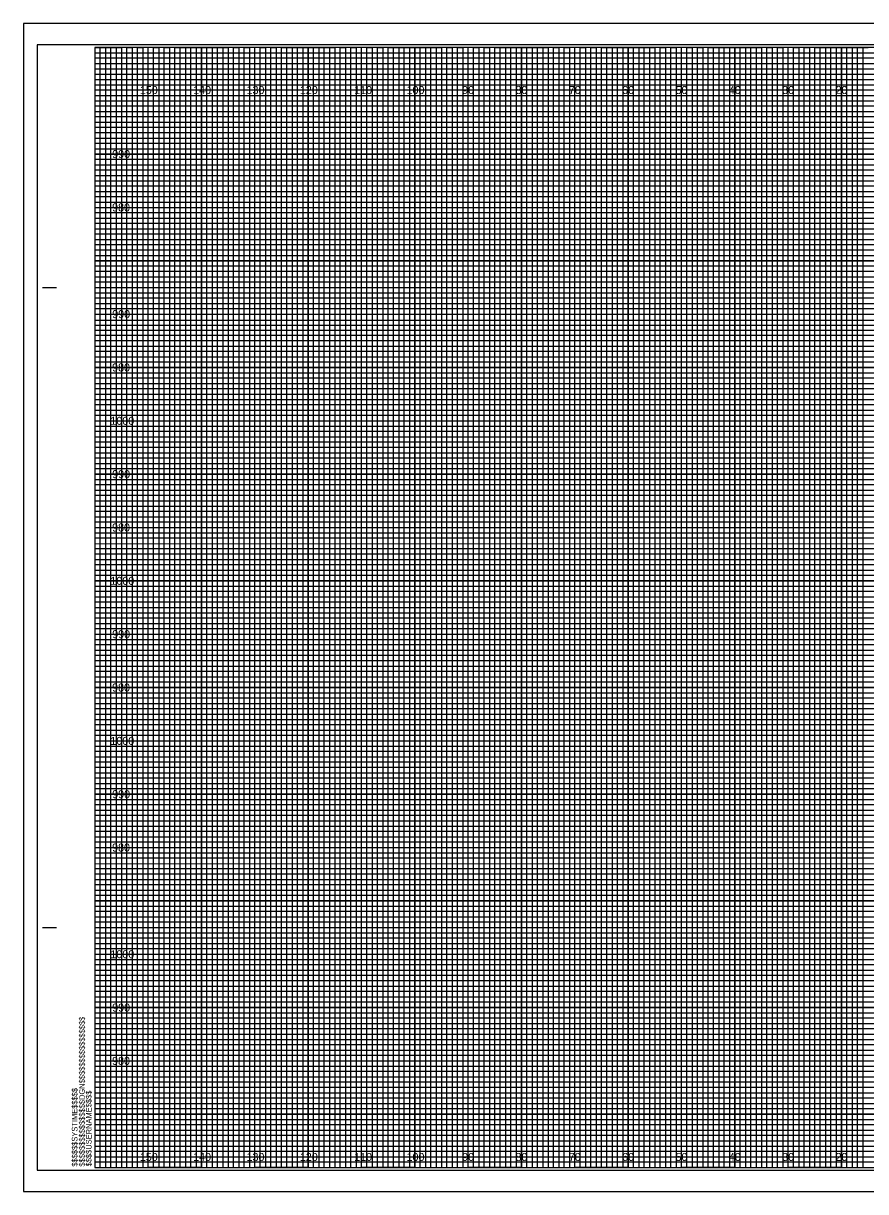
# Model space of a CAD drawing. Extents: x -13 to 323, y -5 to 215.
# Drawn here: x -13.4 to 144.5, y -4.5 to 214.5 of the extents above; entities that cross this region are included whole.
import ezdxf

# ---------------------------------------------------------------- set-up
doc = ezdxf.new("R2010")
doc.units = 0
for name, color, linetype in [('Prop XS Elevation Labels', 7, 'Continuous'), ('Prop XS Offset Labels', 7, 'Continuous'), ('Sheet Cross Section CELL', 7, 'Continuous'), ('Sheet Cross Section Grid Major CELL', 7, 'Continuous'), ('Sheet Cross Section Grid Middle CELL', 7, 'Continuous'), ('Sheet Cross Section Grid Minor 1 CELL', 7, 'Continuous'), ('Sheet Cross Section Grid Minor 2 CELL', 7, 'Continuous'), ('Sheet Cutting Line CELL', 7, 'Continuous'), ('Sheet DOT Grid CELL', 7, 'Continuous'), ('Sheet Plot Border Inside CELL', 7, 'Continuous'), ('Sheet Plot Border Outside CELL', 7, 'Continuous')]:
    doc.layers.add(name, color=color, linetype=linetype)

msp = doc.modelspace()

# ---------------------------------------------------------------- linework, layer by layer
at = {"layer": 'Sheet Cross Section CELL'}
for p, q in [((-9.8, 165), (-7.3, 165)), ((-9.7, 165), (-7.2, 165)), ((-9.8, 45), (-7.3, 45)), ((-9.7, 45), (-7.2, 45))]:
    msp.add_line(p, q, dxfattribs=at)
msp.add_lwpolyline([(320, 210), (0, 210), (0, 0), (320, 0)], close=True, dxfattribs=at)
at = {"layer": 'Sheet Cross Section Grid Major CELL'}
for p, q in [((10, 210), (0, 210)), ((10, 0), (10, 210)), ((30, 210), (20, 210)), ((20, 210), (20, 0)), ((30, 0), (30, 210)), ((50, 210), (40, 210)), ((40, 210), (40, 0)), ((50, 0), (50, 210)), ((70, 210), (60, 210)), ((60, 210), (60, 0)), ((70, 0), (70, 210)), ((90, 210), (80, 210)), ((80, 210), (80, 0)), ((90, 0), (90, 210)), ((110, 210), (100, 210)), ((100, 210), (100, 0)), ((110, 0), (110, 210)), ((130, 210), (120, 210)), ((120, 210), (120, 0)), ((130, 0), (130, 210)), ((150, 210), (140, 210)), ((140, 210), (140, 0)), ((20, 0), (10, 0)), ((40, 0), (30, 0)), ((60, 0), (50, 0)), ((80, 0), (70, 0)), ((100, 0), (90, 0)), ((120, 0), (110, 0)), ((140, 0), (130, 0))]:
    msp.add_line(p, q, dxfattribs=at)
for points in [[(0, 200), (320, 200), (320, 190), (0, 190)], [(0, 180), (320, 180), (320, 170), (0, 170)], [(0, 160), (320, 160), (320, 150), (0, 150)], [(0, 140), (320, 140), (320, 130), (0, 130)], [(0, 120), (320, 120), (320, 110), (0, 110)], [(0, 100), (320, 100), (320, 90), (0, 90)], [(0, 80), (320, 80), (320, 70), (0, 70)], [(0, 60), (320, 60), (320, 50), (0, 50)], [(0, 40), (320, 40), (320, 30), (0, 30)], [(0, 20), (320, 20), (320, 10), (0, 10)]]:
    msp.add_lwpolyline(points, dxfattribs=at)
at = {"layer": 'Sheet Cross Section Grid Middle CELL'}
for points in [[(0, 210), (5, 210), (5, 0), (15, 0), (15, 210), (25, 210), (25, 0), (35, 0), (35, 210), (45, 210), (45, 0), (55, 0), (55, 210), (65, 210), (65, 0), (75, 0), (75, 210), (85, 210), (85, 0), (95, 0), (95, 210), (105, 210), (105, 0), (115, 0), (115, 210), (125, 210), (125, 0), (135, 0), (135, 210), (145, 210)], [(0, 205), (275, 205)], [(0, 185), (320, 185), (320, 195), (0, 195)], [(0, 165), (320, 165), (320, 175), (0, 175)], [(0, 145), (320, 145), (320, 155), (0, 155)], [(0, 125), (320, 125), (320, 135), (0, 135)], [(0, 105), (320, 105), (320, 115), (0, 115)], [(0, 85), (320, 85), (320, 95), (0, 95)], [(0, 65), (320, 65), (320, 75), (0, 75)], [(0, 45), (320, 45), (320, 55), (0, 55)], [(0, 25), (320, 25), (320, 35), (0, 35)], [(0, 5), (320, 5), (320, 15), (0, 15)]]:
    msp.add_lwpolyline(points, dxfattribs=at)
at = {"layer": 'Sheet Cross Section Grid Minor 1 CELL'}
for p, q in [((0, 209), (260, 209)), ((260, 207.98), (0, 207.98)), ((0, 207.98), (0, 207)), ((0, 207), (260, 207)), ((260, 205.89), (0, 205.89)), ((0, 205.89), (0, 204)), ((0, 204), (320, 204))]:
    msp.add_line(p, q, dxfattribs=at)
for points in [[(0, 203), (270, 203), (320, 203), (320, 202), (0, 202)], [(0, 201), (320, 201), (320, 199), (0, 199)], [(0, 198), (320, 198), (320, 197), (0, 196.98)], [(0, 196), (320, 196), (320, 194), (0, 194)], [(0, 193), (320, 193), (320, 192), (0, 192)], [(0, 191), (320, 191), (320, 189), (0, 189)], [(0, 188), (320, 188), (320, 187), (0, 187)], [(0, 186), (320, 186), (320, 184), (0, 184)], [(0, 183), (320, 183), (320, 182), (0, 182)], [(0, 181), (320, 181), (320, 179), (0, 179)], [(0, 178), (320, 178), (320, 177), (0, 177)], [(0, 176), (320, 176), (320, 173.95), (320, 173), (320, 172), (0, 172)], [(0, 174), (320, 174), (320, 173), (0, 173)], [(0, 171), (320, 171), (320, 169), (0, 169.03)], [(0, 169.03), (320, 169), (320, 168), (0, 168)], [(0, 167), (320, 167), (320, 166), (0, 166)], [(0, 164), (320, 164), (320, 163), (0, 163)], [(0, 162), (320, 162), (320, 161), (0, 161)], [(-0.07, 158.89), (320, 158.89), (320, 157.88), (-0.07, 157.88)], [(0, 157), (320, 157), (320, 156), (0, 156)], [(0, 154), (320, 154), (320, 153), (0, 153)], [(0, 152), (320, 152), (320, 151), (0, 151)], [(0, 149), (320, 149), (320, 148), (0, 148)], [(0, 147), (320, 147), (320, 146), (0, 146)], [(0, 144), (320, 144), (320, 143), (0, 143)], [(0, 142), (320, 142), (320, 141), (0, 141)], [(0, 139), (320, 139), (319.99, 137.98), (0, 138)], [(0, 137), (320, 137), (320, 136), (0, 136)], [(0, 134), (320, 134), (320, 133), (0, 133)], [(0, 132), (320, 132), (320, 131), (0, 131)], [(0, 129), (320, 129), (320, 128), (0, 128)], [(0, 127), (320, 127), (320, 126), (0, 126)], [(0, 124), (320, 124), (320, 123), (0, 123)], [(0, 122), (320, 122), (320, 121), (0, 121)], [(0, 119), (320, 119), (320, 118), (0, 118)], [(0, 116.99), (320.07, 116.91), (320, 116), (0, 116)], [(0, 114), (320, 114), (320, 113), (0, 113)], [(0, 112), (320, 112), (320, 111), (0, 111)], [(0, 109), (320, 109), (320, 108), (0, 108)], [(0, 107), (320, 107), (320, 106), (0, 106)], [(0, 104), (320, 104), (320, 103), (0, 103)], [(0, 102), (320, 102), (320, 101), (0, 101)], [(0, 99), (320, 99), (320, 98), (0, 98)], [(0, 97), (320, 97), (320, 96), (0, 96)], [(0, 94), (320, 94), (320, 93), (0, 93)], [(0, 92), (320, 92), (320, 91), (0, 91)], [(0, 89), (320, 89), (320, 88), (0, 88)], [(0, 87), (320, 87), (320, 86), (0, 86)], [(0, 84), (320, 84), (320, 83), (0, 83)], [(0, 82), (320, 82), (320, 81), (0, 81)], [(0, 79), (320, 79), (319.99, 77.98), (0, 78)], [(0, 77), (320, 77), (320, 76), (0, 76)], [(0, 74), (320, 74), (320, 73), (0, 73)], [(0, 72), (320, 72), (320, 71), (0, 71)], [(0, 69), (320, 69), (320, 68), (0, 68)], [(0, 67), (320, 67), (320, 66), (0, 66)], [(0, 64), (320, 64), (320, 63), (0, 63)], [(0, 62), (320, 62), (320, 61), (0, 61)], [(0, 59), (320, 59), (320, 58), (0, 58)], [(0, 56.99), (320.07, 56.91), (320, 56), (0, 56)], [(0, 54), (320, 54), (320, 53), (0, 53)], [(0, 52), (320, 52), (320, 51), (0, 51)], [(0, 49), (320, 49), (320, 48), (0, 48)], [(0, 47), (320, 47), (320, 46), (0, 46)], [(0, 44), (320, 44), (320, 43), (0, 43)], [(0, 42), (320, 42), (320, 41), (0, 41)], [(0, 39), (320, 39), (320, 38), (0, 38)], [(0, 37), (320, 37), (320, 36), (0, 36)], [(0, 34), (320, 34), (320, 33), (0, 33)], [(0, 32), (320, 32), (320, 31), (0, 31)], [(0, 29), (320, 29), (320, 28), (0, 28)], [(0, 27), (320, 27), (320, 26), (0, 26)], [(0, 24), (320, 24), (320, 23), (0, 23)], [(0, 22), (320, 22), (320, 21), (0, 21)], [(0, 19), (320, 19), (320, 18), (0, 18)], [(0, 17), (320, 17), (320, 16), (0, 16)], [(0, 14), (320, 14), (320, 13), (0, 13)], [(0, 12), (320, 12), (320, 11), (0, 11)], [(0, 9), (320, 9), (320, 8), (0, 8)], [(0, 7), (320, 7), (320, 6), (0, 6)], [(0, 4), (320, 4), (320, 3), (0, 3)], [(0, 2), (320, 2), (320, 1), (0, 1)]]:
    msp.add_lwpolyline(points, dxfattribs=at)
at = {"layer": 'Sheet Cross Section Grid Minor 2 CELL'}
for points in [[(0, 0), (1, 0), (1, 210), (2, 210), (2, 0)], [(2, 0), (3, 0), (3, 210), (4, 210), (4, 0)], [(5, 0), (6, 0), (6, 210), (7, 210), (7, 0)], [(7, 0), (8, 0), (8, 210), (9, 210), (9, 0)], [(10, 0), (11, 0), (11, 210), (12, 210), (12, 0)], [(12, 0), (13, 0), (13, 210), (14, 210), (14, 0)], [(15, 0), (16, 0), (16, 210), (17, 210), (17, 0)], [(17, 0), (18, 0), (18, 210), (19, 210), (19, 0)], [(20, 0), (21, 0), (21, 210), (22, 210), (22, 0)], [(22, 0), (23, 0), (23, 210), (24, 210), (24, 0)], [(25, 0), (26, 0), (26, 210), (27, 210), (27, 0)], [(27, 0), (28, 0), (28, 210), (29, 210), (29, 0)], [(30, 0), (31, 0), (31, 210), (32, 210), (32, 0)], [(32, 0), (33, 0), (33, 210), (34, 210), (34, 0)], [(35, 0), (36, 0), (36, 210), (37, 210), (37, 0)], [(37, 0), (38, 0), (38, 210), (39, 210), (39, 0)], [(40, 0), (41, 0), (41, 210), (42, 210), (42, 0)], [(42, 0), (43, 0), (43, 210), (44, 210), (44, 0)], [(45, 0), (46, 0), (46, 210), (47, 210), (47, 0)], [(47, 0), (48, 0), (48, 210), (49, 210), (49, 0)], [(50, 0), (51, 0), (51, 210), (52, 210), (52, 0)], [(52, 0), (53, 0), (53, 210), (54, 210), (54, 0)], [(55, 0), (56, 0), (56, 210), (57, 210), (57, 0)], [(57, 0), (58, 0), (58, 210), (59, 210), (59, 0)], [(60, 0), (61, 0), (61, 210), (62, 210), (62, 0)], [(62, 0), (63, 0), (63, 210), (64, 210), (64, 0)], [(65, 0), (66, 0), (66, 210), (67, 210), (67, 0)], [(67, 0), (68, 0), (68, 210), (69, 210), (69, 0)], [(70, 0), (71, 0), (71, 210), (72, 210), (72, 0)], [(72, 0), (73, 0), (73, 210), (74, 210), (74, 0)], [(75, 0), (76, 0), (76, 210), (77, 210), (77, 0)], [(77, 0), (78, 0), (78, 210), (79, 210), (79, 0)], [(80, 0), (81, 0), (81, 210), (82, 210), (82, 0)], [(82, 0), (83, 0), (83, 210), (84, 210), (84, 0)], [(85, 0), (86, 0), (86, 210), (87, 210), (87, 0)], [(87, 0), (88, 0), (88, 210), (89, 210), (89, 0)], [(90, 0), (91, 0), (91, 210), (92, 210), (92, 0)], [(92, 0), (93, 0), (93, 210), (94, 210), (94, 0)], [(95, 0), (96, 0), (96, 210), (97, 210), (97, 0)], [(97, 0), (98, 0), (98, 210), (99, 210), (99, 0)], [(100, 0), (101, 0), (101, 210), (102, 210), (102, 0)], [(102, 0), (103, 0), (103, 210), (104, 210), (104, 0)], [(105, 0), (106, 0), (106, 210), (107, 210), (107, 0)], [(107, 0), (108, 0), (108, 210), (109, 210), (109, 0)], [(110, 0), (111, 0), (111, 210), (112, 210), (112, 0)], [(112, 0), (113, 0), (113, 210), (114, 210), (114, 0)], [(115, 0), (116, 0), (116, 210), (117, 210), (117, 0)], [(117, 0), (118, 0), (118, 210), (119, 210), (119, 0)], [(120, 0), (121, 0), (121, 210), (122, 210), (122, 0)], [(122, 0), (123, 0), (123, 210), (124, 210), (124, 0)], [(125, 0), (126, 0), (126, 210), (127, 210), (127, 0)], [(127, 0), (128, 0), (128, 210), (129, 210), (129, 0)], [(130, 0), (131, 0), (131, 210), (132, 210), (132, 0)], [(132, 0), (133, 0), (133, 210), (134, 210), (134, 0)], [(135, 0), (136, 0), (136, 210), (137, 210), (137, 0)], [(137, 0), (138, 0), (138, 210), (139, 210), (139, 0)], [(140, 0), (141, 0), (141, 210), (142, 210), (142, 0)], [(142, 0), (143, 0), (143, 210), (144, 210), (144, 0)]]:
    msp.add_lwpolyline(points, dxfattribs=at)
at = {"layer": 'Sheet Cutting Line CELL'}
for p, q in [((323.3, 214.5), (-13.4, 214.5)), ((-13.4, 214.5), (-13.4, -4.5)), ((-13.4, -4.5), (323.3, -4.5))]:
    msp.add_line(p, q, dxfattribs=at)
at = {"layer": 'Sheet DOT Grid CELL'}
for p, q in [((10, 0), (10, 210)), ((20, 0), (20, 210)), ((30, 0), (30, 210)), ((40, 0), (40, 210)), ((50, 0), (50, 210)), ((60, 0), (60, 210)), ((70, 0), (70, 210)), ((80, 0), (80, 210)), ((90, 0), (90, 210)), ((100, 0), (100, 210)), ((110, 0), (110, 210)), ((120, 0), (120, 210)), ((130, 0), (130, 210)), ((140, 0), (140, 210)), ((0, 200), (320, 200)), ((0, 190), (320, 190)), ((0, 180), (320, 180)), ((0, 170), (320, 170)), ((0, 160), (320, 160)), ((0, 150), (320, 150)), ((0, 140), (320, 140)), ((0, 130), (320, 130)), ((0, 120), (320, 120)), ((0, 110), (320, 110)), ((0, 100), (320, 100)), ((0, 90), (320, 90)), ((0, 80), (320, 80)), ((0, 70), (320, 70)), ((0, 60), (320, 60)), ((0, 50), (320, 50)), ((0, 40), (320, 40)), ((0, 30), (320, 30)), ((0, 20), (320, 20)), ((0, 10), (320, 10))]:
    msp.add_line(p, q, dxfattribs=at)
at = {"layer": 'Sheet Plot Border Inside CELL'}
msp.add_lwpolyline([(-10.8, -0.5), (322.4, -0.5), (322.4, 210.5), (-10.8, 210.5)], close=True, dxfattribs=at)
at = {"layer": 'Sheet Plot Border Outside CELL'}
msp.add_lwpolyline([(-13.4, -4.5), (323.3, -4.5), (323.3, 214.5), (-13.4, 214.5)], close=True, dxfattribs=at)

# ---------------------------------------------------------------- texts
at = {"layer": 'Prop XS Elevation Labels'}
for s, p in [('990', (3.26, 189.25)), ('980', (3.24, 179.25)), ('990', (3.26, 159.25)), ('980', (3.24, 149.25)), ('1000', (2.92, 139.25)), ('990', (3.26, 129.25)), ('980', (3.24, 119.25)), ('1000', (2.92, 109.25)), ('990', (3.26, 99.25)), ('980', (3.24, 89.25)), ('1000', (2.92, 79.25)), ('990', (3.26, 69.25)), ('980', (3.24, 59.25)), ('1000', (2.92, 39.25)), ('990', (3.26, 29.25)), ('980', (3.24, 19.25))]:
    msp.add_text(s, height=1.5, dxfattribs=at).set_placement(p)
at = {"layer": 'Prop XS Offset Labels'}
for s, p in [('150', (8.44, 201.25)), ('140', (18.44, 201.25)), ('130', (28.44, 201.25)), ('120', (38.44, 201.25)), ('110', (48.62, 201.25)), ('100', (58.44, 201.25)), ('90', (68.86, 201.25)), ('80', (78.86, 201.25)), ('70', (88.86, 201.25)), ('60', (98.86, 201.25)), ('50', (108.86, 201.25)), ('40', (118.86, 201.25)), ('30', (128.86, 201.25)), ('20', (138.86, 201.25)), ('150', (8.44, 1.25)), ('140', (18.44, 1.25)), ('130', (28.44, 1.25)), ('120', (38.44, 1.25)), ('110', (48.62, 1.25)), ('100', (58.44, 1.25)), ('90', (68.86, 1.25)), ('80', (78.86, 1.25)), ('70', (88.86, 1.25)), ('60', (98.86, 1.25)), ('50', (108.86, 1.25)), ('40', (118.86, 1.25)), ('30', (128.86, 1.25)), ('20', (138.86, 1.25))]:
    msp.add_text(s, height=1.5, dxfattribs=at).set_placement(p)
at = {"layer": 'Sheet Cross Section CELL'}
for s, p in [('$$$$$$$$$$$$$$$$DGN$$$$$$$$$$$$$$$$', (-1.88, 0.18)), ('$$$$$$SYSTIME$$$$$', (-3.26, 0.18)), ('$$$$USERNAME$$$$', (-0.62, 0.23))]:
    msp.add_text(s, height=1.05, rotation=90, dxfattribs=at).set_placement(p)

doc.saveas('drawing.dxf')
